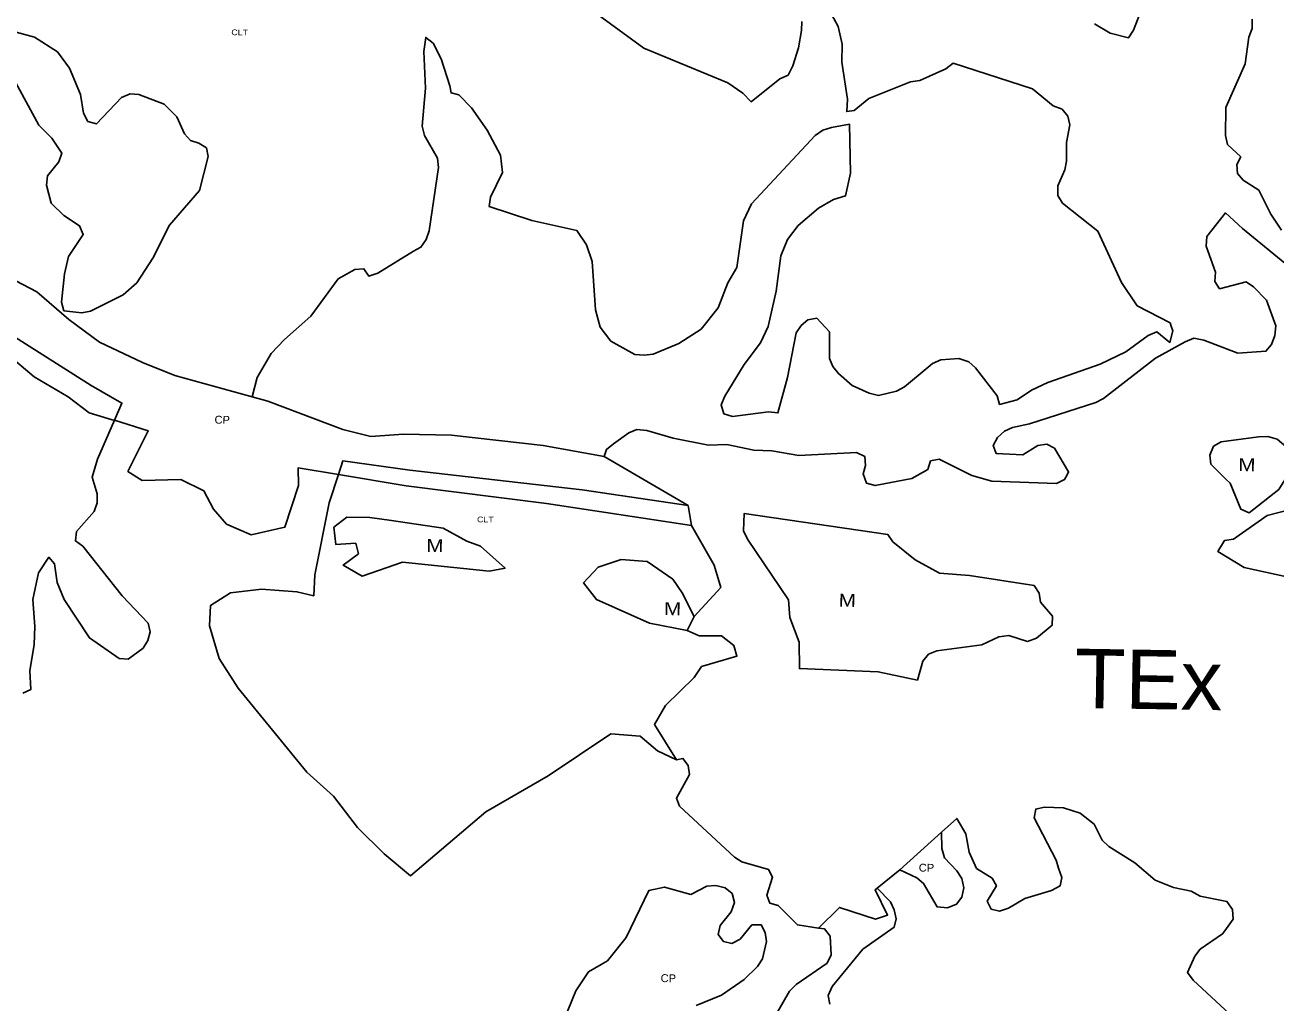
# Model space of a CAD drawing. Extents: x 713589 to 726391, y 7177764 to 7191819.
# Drawn here: x 716445 to 717458, y 7180202 to 7180995 of the extents above; entities that cross this region are included whole.
import ezdxf
from ezdxf.enums import TextEntityAlignment as Align

# ---------------------------------------------------------------- set-up
doc = ezdxf.new("R2010")
doc.units = 0
doc.header["$LTSCALE"] = 2.6
doc.layers.add('63', color=7, linetype='Continuous', lineweight=25)

msp = doc.modelspace()

# ---------------------------------------------------------------- linework, layer by layer
at = {"layer": '63'}
for p, q in [((716982.1, 7180605.4), (716914.15, 7180644.97)), ((716984.69, 7180588.99), (716982.1, 7180605.4)), ((716981.29, 7180503.92), (716987.04, 7180515.19)), ((717187.5, 7180340.59), (717153.55, 7180310)), ((717153.55, 7180310), (717135.19, 7180295.16))]:
    msp.add_line(p, q, dxfattribs=at)
for points in [[(717096.66, 7181006.37), (717103.56, 7180993.54), (717106.85, 7180979.06), (717106.52, 7180964.58), (717111.12, 7180934.63), (717110.68, 7180924.44), (717116.58, 7180925.29), (717128.43, 7180935.16), (717162.33, 7180948.64), (717169.9, 7180949.63), (717190.96, 7180959.17), (717196.85, 7180963.74), (717261.18, 7180942.83), (717277.96, 7180929.01), (717285.2, 7180926.38), (717289.81, 7180920.78), (717291.45, 7180913.87), (717288.81, 7180899.39), (717288.81, 7180884.26), (717287.49, 7180877.34), (717281.57, 7180864.18), (717281.57, 7180856.61), (717285.52, 7180850.36), (717314.14, 7180827.65), (717333.22, 7180785.86), (717346.05, 7180767.1), (717372.7, 7180753.27), (717373.6, 7180750.71), (717375, 7180746.69), (717372.51, 7180737.49), (717362, 7180745.96), (717354.93, 7180743.07), (717336.83, 7180729.91), (717316.1, 7180719.72), (717273.64, 7180704.91), (717260.48, 7180698.66), (717248.63, 7180690.77), (717234.48, 7180687.15), (717232.51, 7180694.06), (717215.07, 7180716.77), (717209.48, 7180721.71), (717201.58, 7180724.34), (717186.77, 7180723.36), (717180.19, 7180720.4), (717176.72, 7180717.49), (717157.48, 7180701.31), (717150.9, 7180698.03), (717136.42, 7180694.41), (717128.85, 7180696.38), (717115.03, 7180702.64), (717103.84, 7180712.18), (717099.24, 7180717.78), (717096.61, 7180724.36), (717096.61, 7180746.08), (717086.41, 7180756.94), (717079.17, 7180755.63), (717073.58, 7180751.02)], [(717351.36, 7181012.12), (717343.13, 7180990.4), (717338.85, 7180984.15), (717324.04, 7180988.1), (717311.54, 7180995.67)], [(716909.28, 7181002.98), (716946.13, 7180975.99), (717014.25, 7180947.68), (717026.42, 7180939.45), (717033.07, 7180932.39), (717056.5, 7180951.1), (717063.08, 7180954.06), (717067.03, 7180961.63), (717071.64, 7180976.1), (717073.95, 7180990.25), (717074.28, 7180997.49)], [(717439.22, 7180999.27), (717439.22, 7180991.7), (717436.58, 7180984.79), (717433.62, 7180963.07), (717417.82, 7180927.87), (717417.48, 7180905.16), (717419.13, 7180897.92), (717429.98, 7180887.72), (717426.69, 7180881.47), (717427.35, 7180874.23), (717431.96, 7180868.96), (717444.46, 7180860.73), (717454.33, 7180841.32), (717462.88, 7180828.48)], [(716430.14, 7180960.65), (716455.91, 7180913.55), (716466.5, 7180902.93), (716474.43, 7180890.65), (716472.1, 7180883.7), (716462.8, 7180872.44), (716462.13, 7180864.82), (716465.75, 7180850.23), (716476, 7180840.27), (716488.92, 7180831.97), (716491.89, 7180825), (716479.93, 7180807.13), (716476.59, 7180792.88), (716474.23, 7180770.02), (716476.21, 7180763.06), (716490.79, 7180761.37), (716497.75, 7180762.69), (716524.28, 7180775.9), (716535.24, 7180785.82), (716548.2, 7180805.69), (716561.83, 7180832.51), (716586.07, 7180860.64), (716593.07, 7180888.14), (716591.76, 7180895.1), (716585.47, 7180898.75), (716578.84, 7180901.08), (716573.88, 7180906.39), (716567.61, 7180920.32), (716557.35, 7180930.62), (716536.82, 7180938.27), (716529.86, 7180938.95), (716522.89, 7180935.97), (716502.64, 7180914.47), (716495.68, 7180916.47), (716492.05, 7180923.1), (716489.76, 7180938.35), (716480.84, 7180959.57), (716470.92, 7180972.85), (716452.38, 7180984.81), (716431.51, 7180990.48)], [(717073.58, 7180751.02), (717069.63, 7180745.1), (717062.71, 7180708.9), (717054.81, 7180680.27), (717047.24, 7180681.26), (717017.95, 7180677.32), (717011.04, 7180679.62), (717008.74, 7180686.86), (717011.7, 7180693.77), (717027.5, 7180719.44), (717040.67, 7180737.2), (717046.92, 7180750.37), (717053.51, 7180778.99), (717057.13, 7180807.62), (717062.73, 7180820.78), (717071.29, 7180832.3), (717087.74, 7180846.12), (717099.92, 7180853.36), (717109.64, 7180856.2), (717113.61, 7180874.61), (717112.93, 7180914.22), (717098.29, 7180911.6), (717091.37, 7180909.3), (717085.12, 7180905.02), (717033.45, 7180849.75), (717026.86, 7180835.93), (717021.59, 7180798.09), (717014.35, 7180785.58), (717006.45, 7180765.51), (716992.62, 7180748.07), (716974.52, 7180736.56), (716953.79, 7180728.01), (716946.55, 7180727.02), (716938.98, 7180727.68), (716919.57, 7180738.54), (716910.69, 7180749.73), (716907.07, 7180763.88), (716904.44, 7180803.04), (716899.84, 7180816.53), (716891.94, 7180828.05), (716855.42, 7180836.29), (716820.87, 7180847.48), (716821.86, 7180855.05), (716831.73, 7180875.12), (716830.09, 7180889.27), (716819.23, 7180909.35), (716806.4, 7180927.45), (716796.2, 7180937.98), (716790.02, 7180939.6), (716788.92, 7180945.23), (716782.02, 7180967.27), (716775.51, 7180979.89), (716769.48, 7180984.61), (716767.91, 7180973.2), (716769.22, 7180943.58), (716766.58, 7180912.65), (716768.56, 7180905.08), (716779.08, 7180886.65), (716779.74, 7180879.08), (716772.16, 7180827.75), (716769.86, 7180820.84), (716765.58, 7180814.58), (716759.63, 7180811.26), (716730.48, 7180793.53), (716723.22, 7180791.24), (716719.27, 7180797.18), (716712.02, 7180796.53), (716698.48, 7180788.97), (716676.33, 7180758.66), (716654.85, 7180739.89), (716644.28, 7180728.36), (716632.7, 7180708.92), (716628.77, 7180693.32)], [(716914.15, 7180644.97), (716915.93, 7180650.68), (716921.53, 7180655.29), (716934.04, 7180664.17), (716940.62, 7180666.8), (716948.52, 7180666.14), (716969.9, 7180659.89), (716998.53, 7180654.29), (717013.34, 7180654.61), (717035.39, 7180650), (717049.87, 7180649.67), (717071.91, 7180645.72), (717118.64, 7180648.34), (717125.22, 7180645.05), (717125.88, 7180637.81), (717123.9, 7180630.9), (717126.53, 7180623.33), (717133.77, 7180621.36), (717163.39, 7180627.27), (717176.23, 7180634.51), (717178.53, 7180641.42), (717185.44, 7180642.74), (717212.09, 7180629.57), (717228.22, 7180624.96), (717280.54, 7180622.97), (717287.12, 7180626.26), (717288.9, 7180629.66), (717290.41, 7180632.52), (717278.9, 7180651.6), (717272.65, 7180654.9), (717265.41, 7180653.91), (717253.23, 7180646.34), (717231.84, 7180647.33), (717229.21, 7180653.92), (717232.83, 7180660.5), (717238.43, 7180665.43), (717245.01, 7180668.39), (717258.83, 7180671.35), (717312.47, 7180688.78), (717318.72, 7180692.07), (717360.85, 7180724.64), (717384.87, 7180737.8), (717391.79, 7180740.76), (717400.01, 7180739.12), (717427.65, 7180728.58), (717450.36, 7180730.22), (717454.97, 7180735.82), (717457.6, 7180743.05), (717458.26, 7180750.95), (717450.7, 7180771.68), (717440.17, 7180782.55), (717434.24, 7180786.5), (717412.85, 7180780.91), (717408.91, 7180786.83), (717409.57, 7180794.4), (717402, 7180815.46), (717402.33, 7180823.36), (717417.63, 7180842.32), (717431.49, 7180829.8), (717474.59, 7180794.25)], [(716628.77, 7180693.32), (716566.07, 7180710.68), (716539.83, 7180721.05), (716504.98, 7180737.72), (716480.09, 7180756.04), (716454.21, 7180778.34), (716414.71, 7180799), (716368.24, 7180820.34), (716344.12, 7180835.72)], [(716517.22, 7180674.4), (716523.25, 7180688.25), (716498.27, 7180702.52), (716430.9, 7180745.16)], [(716442.84, 7180453.32), (716449.47, 7180456.29), (716448.5, 7180471.21), (716452.18, 7180492.74), (716452.54, 7180507.33), (716450.92, 7180529.2), (716455.59, 7180550.73), (716463.9, 7180563.31), (716468.53, 7180558), (716470.83, 7180542.76), (716476.44, 7180529.16), (716496.93, 7180497.97), (716521.1, 7180481.36), (716528.39, 7180480.69), (716540.33, 7180489.61), (716544.32, 7180495.9), (716545.99, 7180502.86), (716544.35, 7180509.82), (716523.5, 7180532.06), (716491.42, 7180572.22), (716485.46, 7180576.54), (716486.47, 7180584.16), (716500.75, 7180600.37), (716503.08, 7180607.33), (716503.09, 7180614.62), (716499.14, 7180628.21), (716503.47, 7180642.79), (716517.22, 7180674.4), (716515.21, 7180674.81), (716496.57, 7180680.25), (716479.69, 7180693.2), (716452.02, 7180709.47), (716429.05, 7180729.08)], [(716914.15, 7180644.97), (716864.51, 7180653.78), (716790.3, 7180662.15), (716751.38, 7180663.2), (716724.99, 7180661.26), (716702.23, 7180666.91), (716641.58, 7180689.77), (716628.77, 7180693.32)], [(716517.22, 7180674.4), (716544.48, 7180665.77), (716528, 7180632.89), (716539.54, 7180625.61), (716570.88, 7180626.22), (716589.66, 7180617.28), (716597.56, 7180602.43), (716608.09, 7180590.2), (716627.87, 7180581.59), (716655.26, 7180587.82), (716666.2, 7180621.45), (716665.97, 7180635.79), (716698.69, 7180630.26)], [(716982.1, 7180605.4), (716896.18, 7180617.97), (716756.52, 7180633.91), (716702.37, 7180641.51), (716698.69, 7180630.26)], [(716698.69, 7180630.26), (716691.25, 7180607.55), (716679.61, 7180549.18), (716678.65, 7180532.1), (716665.07, 7180535.35), (716636.37, 7180537.38), (716611.3, 7180534.45), (716595.12, 7180524.25), (716594.1, 7180507.76), (716601.97, 7180481.36), (716617.44, 7180457.25), (716673.06, 7180389.23), (716694.81, 7180369.7), (716714.24, 7180344.27), (716735.64, 7180323.12), (716757.05, 7180305.27), (716818.17, 7180356.96), (716868.69, 7180386.24), (716919.54, 7180420.13), (716943.29, 7180418.44), (716957.13, 7180406.54), (716972.54, 7180399.26)], [(716698.69, 7180630.26), (716753.62, 7180621.3), (716867.4, 7180606.93), (716984.69, 7180588.99)], [(717484.66, 7180543.71), (717432.67, 7180554.91), (717411.28, 7180568.08), (717416.87, 7180576.93), (717424.07, 7180578), (717451.39, 7180597.08), (717469.16, 7180601.68)], [(716987.04, 7180515.19), (717008.54, 7180538.81), (717003.19, 7180557.01), (716984.69, 7180588.99)], [(716987.04, 7180515.19), (716977.23, 7180534.59), (716969.66, 7180545.45), (716948.93, 7180559.93), (716927.87, 7180561.58), (716909.12, 7180555.33), (716897.27, 7180542.5), (716907.79, 7180529.01), (716950.9, 7180509.91), (716981.29, 7180503.92)], [(716972.54, 7180399.26), (716954.81, 7180427.71), (716963.7, 7180443.18), (716987.07, 7180465.88), (716992.99, 7180474.76), (717021.62, 7180483.31), (717018.99, 7180491.87), (717009.12, 7180499.77), (716991.02, 7180499.77), (716981.29, 7180503.92)], [(716972.54, 7180399.26), (716977.84, 7180400.39), (716982.12, 7180394.47), (716983.11, 7180387.23), (716972.57, 7180368.15), (716975.2, 7180361.56), (717019.62, 7180320.42), (717025.54, 7180316.47), (717047.26, 7180310.22), (717050.55, 7180303.96), (717045.94, 7180289.48), (717048.24, 7180282.9), (717055.15, 7180281.26), (717070.62, 7180265.46), (717087.84, 7180262.88)], [(717187.5, 7180340.59), (717199.76, 7180351.64), (717207.2, 7180339.15), (717209.83, 7180324.34), (717215.75, 7180311.17), (717228.58, 7180303.27), (717231.87, 7180297.02), (717224.3, 7180284.52), (717227.59, 7180278.26), (717234.5, 7180276.62), (717241.74, 7180278.92), (717254.9, 7180286.82), (717276.62, 7180293.39), (717283.53, 7180297.01), (717284.85, 7180303.92), (717282.37, 7180311.37), (717280.25, 7180317.74), (717262.48, 7180352.3), (717263.8, 7180359.21), (717270.71, 7180360.85), (717286.18, 7180360.19), (717299.67, 7180355.91), (717311.18, 7180347.03), (717317.76, 7180334.19), (717323.03, 7180328.92), (717344.08, 7180315.76), (717360.54, 7180301.61), (717375.34, 7180295.68), (717389.82, 7180292.72), (717397.06, 7180288.76), (717418.78, 7180284.48), (717423.38, 7180277.9), (717423.71, 7180270), (717416.91, 7180260.6), (717415.15, 7180258.16), (717397.05, 7180245.66), (717392.77, 7180240.06), (717386.85, 7180226.9), (717391.45, 7180220.65), (717432.03, 7180183.18)], [(717153.55, 7180310), (717167.37, 7180303.61), (717172.96, 7180299.01), (717183.82, 7180279.92), (717192.38, 7180279.26), (717199.62, 7180282.22), (717203.9, 7180287.81), (717205.54, 7180295.38), (717203.9, 7180302.95), (717199.95, 7180309.2), (717189.75, 7180319.73), (717187.78, 7180327.3), (717187.5, 7180340.59)], [(716877.58, 7180178.73), (716891.16, 7180212.03), (716901.41, 7180227.51), (716916.6, 7180236.4), (716931.81, 7180255.17), (716950.34, 7180293.41), (716962.88, 7180296.03), (716984.31, 7180290.05), (716997.24, 7180296.73), (717004.48, 7180297.39), (717012.05, 7180295.41), (717017.64, 7180290.81), (717019.62, 7180283.57), (717016.98, 7180276), (717008.09, 7180264.81), (717006.45, 7180257.57), (717010.72, 7180251.98), (717017.63, 7180250.33), (717024.22, 7180253.95), (717033.76, 7180265.46), (717041.33, 7180265.46), (717044.62, 7180259.21), (717045.61, 7180251.97), (717042.31, 7180237.82), (717038.36, 7180231.57), (717027.5, 7180221.04), (717009.07, 7180208.54), (716988.67, 7180199.99)], [(717135.19, 7180295.16), (717133.62, 7180293.91), (717143.67, 7180273.34), (717133.8, 7180270.05), (717104.84, 7180279.6), (717087.84, 7180262.88)], [(717096.93, 7180201.28), (717095.62, 7180208.2), (717098.91, 7180215.43), (717123.59, 7180245.7), (717148.94, 7180263.47), (717150.58, 7180270.38), (717148.94, 7180277.62), (717145.98, 7180284.2), (717135.19, 7180295.16)], [(717087.84, 7180262.88), (717092.67, 7180262.16), (717097.27, 7180256.24), (717097.93, 7180241.1), (717094.63, 7180234.52), (717069.62, 7180217.09), (717064.36, 7180211.82), (717052.84, 7180192.08)]]:
    msp.add_lwpolyline(points, dxfattribs=at)
for points in [[(717405.59, 7180638.75), (717417.95, 7180626.64), (717421.38, 7180623.28), (717429.93, 7180602.22), (717436.84, 7180599.25), (717460.87, 7180618.34), (717471.07, 7180634.65), (717476.92, 7180644.01), (717476.67, 7180644.33), (717459.56, 7180659.14), (717451.99, 7180661.12), (717444.42, 7180660.79), (717414.15, 7180656.85), (717407.9, 7180653.23), (717404.93, 7180645.99)], [(717257.24, 7180495.12), (717264.48, 7180497.75), (717276.99, 7180508.28), (717277.32, 7180515.52), (717267.78, 7180527.03), (717266.46, 7180534.27), (717262.51, 7180540.53), (717210.19, 7180548.43), (717185.84, 7180550.41), (717166.1, 7180561.28), (717148, 7180575.76), (717144.01, 7180581.71), (717027.36, 7180598.78), (717026.91, 7180584.66), (717030.2, 7180578.08), (717063.42, 7180528.72), (717064.41, 7180514.57), (717071.97, 7180494.49), (717072.28, 7180473.18), (717136.05, 7180470.44), (717167.91, 7180463.84), (717172.34, 7180479.01), (717176.95, 7180484.93), (717183.53, 7180487.56), (717220.06, 7180492.49), (717233.88, 7180498.74), (717242.1, 7180500.06)], [(716712.66, 7180574.78), (716714.97, 7180566.23), (716702.46, 7180557.01), (716717.92, 7180548.13), (716750.5, 7180559.31), (716820.92, 7180552.06), (716833.76, 7180554.36), (716813.71, 7180572.42), (716802.83, 7180576.41), (716783.42, 7180586.94), (716741.62, 7180593.2), (716724.18, 7180595.51), (716705.43, 7180595.84), (716694.9, 7180587.62), (716696.54, 7180573.8)]]:
    msp.add_lwpolyline(points, close=True, dxfattribs=at)

# ---------------------------------------------------------------- texts
for s, height, width, p in [('CLT', 4.64, 1.15, (716618.6, 7180986.31)), ('CP', 6.4, 1.05, (716604.47, 7180671.53)), ('M', 10.4, 1.2, (717434.87, 7180633.05)), ('CLT', 4.64, 1.15, (716817.76, 7180591.58)), ('M', 10.4, 1.2, (716776.78, 7180567.56)), ('M', 10.4, 1.2, (717111.03, 7180523.23)), ('M', 10.4, 1.2, (716969.42, 7180516.38)), ('TEx', 48, 1.05, (717354.81, 7180440.34)), ('CP', 6.4, 1.05, (717175.2, 7180308.53)), ('CP', 6.4, 1.05, (716966, 7180219))]:
    msp.add_text(s, height=height, rotation=359.062, dxfattribs=dict(at, width=width)).set_placement(p, align=Align.CENTER)

doc.saveas('drawing.dxf')
